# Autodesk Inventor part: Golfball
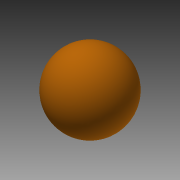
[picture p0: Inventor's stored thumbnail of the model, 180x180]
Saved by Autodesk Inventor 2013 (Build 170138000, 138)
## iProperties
Created: 2012-07
Part Number: Golfball
Material: Golfball
Document SubType Name: Modeling
Designer: rYan
Mass: 44.1276 g
Surface Area: 58.088 cm^2
Volume: 41.6298 cm^3
Density: 1.06 g/cm^3
Author: rYan
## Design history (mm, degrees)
sketch "Skizze1"
  geometry: L1 (-21.5, 0)-(21.5, 0); L2 (-30.1, 0)-(30.1, 0) reference; A1 r 21.5 centre (0, 0) between (-21.5, 0) and (21.5, 0); 1 further point
  constraints: 2 end point, 2 point on circle, 1 centre point, 1 coincident, 1 collinear, 1 horizontal
  dimensions: "d0" = 43 diameter of A1
revolve "Umdrehung1" sketch "Skizze1" stored, may be unused: angle "d2" = 90 deg
node "Volumenkörper1"
